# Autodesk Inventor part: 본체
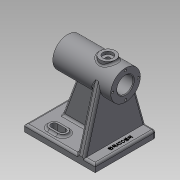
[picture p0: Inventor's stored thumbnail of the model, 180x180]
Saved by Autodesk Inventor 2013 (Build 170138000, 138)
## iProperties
Created: 2019-10
Part Number: 본체
Material: 일반
Document SubType Name: Modeling
Designer: hana-max10
Density: 1 g/cm^3
Author: hana-max10
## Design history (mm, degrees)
sketch "스케치1"
  geometry: L1 (-47.727, 63.797)-(52.273, 63.797); L2 (52.273, 63.797)-(52.273, -22.203); L3 (52.273, -22.203)-(-47.727, -22.203); L4 (-47.727, -22.203)-(-47.727, 63.797); 1 further point
  constraints: 8 end point, 2 parallel, 1 horizontal, 1 perpendicular
  dimensions: "d0" = 100 distance of L2.end L3.end; "d2" = 86 distance of L1.end L2.end
extrude "돌출1" new body sketch "스케치1" distance "d3" = 10; taper "d4" = 0 deg
node "작업 평면1"
sketch "스케치2"
  geometry: L1 (52.273, 63.797)-(-47.727, 63.797) reference; L2 (-47.727, 63.797)-(-47.727, -22.203) reference; L3 (-47.727, -22.203)-(52.273, -22.203) reference; L4 (52.273, -22.203)-(52.273, 63.797) reference; L5 (-47.727, 20.797)-(111.797, 20.797); L6 (52.273, 41.797)-(-29.727, 41.797); L7 (-29.727, 41.797)-(-29.727, 35.297); L8 (-29.727, 35.297)-(32.273, 35.297); L9 (32.273, 35.297)-(32.273, 32.297); L10 (32.273, 32.297)-(52.273, 32.297); L11 (52.273, 32.297)-(52.273, 41.797); 1 further point
  constraints: 14 end point, 4 horizontal, 3 vertical, 1 midpoint
  dimensions: "d6" = 82 distance of L6.start L6.end; "d8" = 9.5 distance of L10.end L6.start; "d9" = 6.5 distance of L6.end L7.end; "d10" = 62 distance of L7.end L8.end; "d11" = 23 diameter of L10 L5; "d12" = 0 distance between parallel lines of L4 L11
revolve "회전1" sketch "스케치2" stored, may be unused: angle "d13" = 90 deg
node "작업 평면2"
sketch "스케치3"
  geometry: L1 (47.727, 0)-(47.727, 10) reference; L2 (32.727, 10)-(-27.273, 10); L3 (-27.273, 10)-(-27.273, 67); L4 (-27.273, 67)-(11.981, 67); L5 (11.981, 67)-(32.727, 10); L6 (-52.273, 0)-(-52.273, 10) reference; L7 (47.727, 10)-(-52.273, 10) reference; L8 (-52.273, 107)-(-52.273, 65) reference; L9 (29.727, 107)-(29.727, 65) reference; 1 further point
  constraints: 8 end point, 2 horizontal, 1 vertical
  dimensions: "d19" = 70 deg angle of L2 L5; "d20" = 15 distance from line of L1 L2.start; "d21" = 25 distance between parallel lines of L6 L3; "d22" = 0 distance between parallel lines of L7 L2; "d23" = 57 distance of L2.end L3.end
extrude "돌출2" join sketch "스케치3" stored distance "d24" = 10; taper "d25" = 0 deg
sketch "스케치4"
  geometry: L1 (0, 0)-(-55.555, 0) reference; L2 (-55.655, 10)-(0, 10) reference; L3 (-81.642, -15.431)-(0, -38.203); L4 (0, -38.203)-(0, 47.797); L5 (0, 47.797)-(-81.642, 25.025); L6 (0, -38.203)-(0, 47.797) reference; L7 (-76, 4.797)-(20.74, 4.797); A1 r 21 centre (-76, 4.797) between (-55.555, 0) and (-55.655, 10) reference; A2 r 21 centre (-76, 4.797) between (-55.655, 10) and (-55.555, 0) reference; A3 r 21 centre (-76, 4.797) between (-81.642, -15.431) and (-81.642, 25.025); 1 further point
  constraints: 8 end point, 3 point on circle, 2 tangent, 1 centre point, 1 coincident, 1 horizontal, 1 vertical, 1 other
  dimensions: "d26" = 0 distance between parallel lines of L4 L6; "d27" = 86 distance of L3.end L4.end
extrude "돌출3" join sketch "스케치4" distance "d28" = 10; taper "d29" = 0 deg
node "작업 평면3"
sketch "스케치5"
  geometry: L1 (-21.727, 52.297)-(-9.727, 52.297); L2 (-21.727, 43.297)-(-9.727, 43.297); L3 (27.273, 63.797)-(-47.727, 63.797) reference; L4 (-47.727, 63.797)-(-47.727, -22.203) reference; L5 (27.273, 16)-(-32.727, 16) reference; L6 (-32.727, 26)-(27.273, 26) reference; L7 (-32.727, 16)-(-32.727, 26) reference; L8 (-32.727, 21)-(62.617, 21); L9 (-47.727, -21.797)-(-47.727, 64.203); L10 (-21.727, 54.797)-(-9.727, 54.797); L11 (-21.727, 40.797)-(-9.727, 40.797); A1 r 4.5 centre (-21.727, 47.797) between (-21.727, 52.297) and (-21.727, 43.297); A2 r 4.5 centre (-9.727, 47.797) between (-9.727, 43.297) and (-9.727, 52.297); A3 r 7 centre (-9.727, 47.797) between (-9.727, 40.797) and (-9.727, 54.797); A4 r 7 centre (-21.727, 47.797) between (-21.727, 54.797) and (-21.727, 40.797)
  constraints: 12 end point, 8 point on circle, 7 tangent, 4 centre point, 2 coincident, 2 symmetric about line, 1 horizontal, 1 midpoint, 1 parallel
  dimensions: "d31" = 9 diameter of A1; "d33" = 9 diameter of A2; "d34" = 16 distance from line of L3 A1.centre; "d35" = 26 distance from line of L4 A1.centre; "d36" = 12 distance of A2.centre A1.centre; "d37" = 16 distance from line of L3 A2.centre; "d39" = 14 diameter of A3; "d41" = 7 radius of A4
extrude "돌출4" join sketch "스케치5" distance "d42" = 3; taper "d43" = 0 deg
sketch "스케치6" dims "d61" = 10
  geometry: L1 (-21.727, 52.297)-(-9.727, 52.297); L2 (-21.727, 43.297)-(-9.727, 43.297); L3 (27.273, 63.797)-(-47.727, 63.797) reference; L4 (-47.727, 63.797)-(-47.727, -22.203) reference; L5 (-21.727, -1.703)-(-9.727, -1.703); L6 (-21.727, -10.703)-(-9.727, -10.703); A1 r 4.5 centre (-21.727, 47.797) between (-21.727, 52.297) and (-21.727, 43.297); A2 r 4.5 centre (-9.727, 47.797) between (-9.727, 43.297) and (-9.727, 52.297); A3 r 4.5 centre (-9.727, -6.203) between (-9.727, -10.703) and (-9.727, -1.703); A4 r 4.5 centre (-21.727, -6.203) between (-21.727, -1.703) and (-21.727, -10.703); 1 further point
  constraints: 8 end point, 8 point on circle, 4 centre point, 3 tangent, 1 parallel, 1 vertical, 10 other
  dimensions: "d44" = 12 distance of A2.centre A1.centre; "d46" = 9 diameter of A2; "d47" = 9 diameter of A1; "d48" = 16 distance from line of A1.centre L3; "d49" = 26 distance from line of L4 A1.centre; "d50" = 16 distance from line of L3 A2.centre; "d58" = 54 distance of L1.start L5.start
extrude "돌출5" cut sketch "스케치6" stored distance "d51" = 3; taper "d52" = 0 deg
fillet "모깎기1" dims "d63" = 3
fillet "모깎기2" dims "d64" = 3
chamfer "모따기1" distance "d65" = 1; stored, may be unused: second distance "d66" = 2, angle "d67" = 45 deg
fillet "모깎기3" dims "d68" = 3
fillet "모깎기4" dims "d69" = 3
node "작업 평면4"
sketch "스케치9"
  geometry: L1 (-52.273, 41.797)-(-52.273, -0.203) reference; L2 (-52.273, 20.797)-(59.849, 20.797); C1 r 11 at (-27.273, 20.797); 2 further points
  constraints: 2 end point, 1 centre point, 1 coincident, 1 horizontal, 1 midpoint, 1 point on line
  dimensions: "d71" = 22 diameter of C1; "d73" = 25 distance from line of L1 C1.centre
extrude "돌출6" join sketch "스케치9" stored distance "d74" = 3; taper "d75" = 0 deg
fillet "모깎기5" dims "d76" = 3
sketch "스케치11"
  geometry: A1 r 11 centre (27.273, 20.797) between (38.273, 20.797) and (16.273, 20.797) reference; 2 further points
  constraints: 1 coincident
hole "구멍1" sketch "스케치11" at (27.273, 20.797) diameter "d77" = 6; stored, may be unused: countersink angle "d81" = 90 deg, drill point angle "d83" = 118 deg; dims "d78" = 6, "d79" = 14, "d80" = 4, "d82" = 20
sketch "스케치12"
  geometry: L1 (40.684, 1.326)-(40.684, 42.805); L2 (40.684, 42.805)-(46.688, 42.805); L3 (46.688, 42.805)-(46.688, 1.326); L4 (46.688, 1.326)-(40.684, 1.326); 1 further point
  constraints: 2 other
feature "엠보싱1" sketch "스케치12" dims "d0" = 100, "d2" = 86, "d13" = 90 deg, "d84" = 0.5, "d85" = 0
sketch "스케치13" dims "d86" = 36
  geometry: L1 (18, 0)-(0, 0); C1 r 15.5 at (0, 0) reference; 2 further points
  constraints: 2 coincident, 2 end point, 1 horizontal, 1 horizontal alignment, 2 other
hole "구멍2" sketch "스케치13" at (18, 0) diameter "d88" = 3.242; stored, may be unused: countersink angle "d92" = 90 deg, drill point angle "d94" = 118 deg; dims "d89" = 6, "d90" = 14, "d91" = 4, "d93" = 8
sketch "스케치14" dims "d19" = 70 deg, "d20" = 15, "d21" = 25, "d22" = 0, "d23" = 57, "d99" = 36
  geometry: L1 (0, 0)-(-18, 0); C1 r 12.5 at (0, 0) reference; 2 further points
  constraints: 2 coincident, 2 end point, 1 horizontal, 1 horizontal alignment, 2 other
hole "구멍3" sketch "스케치14" at (-18, 0) diameter "d100" = 3.242; stored, may be unused: countersink angle "d104" = 90 deg, drill point angle "d106" = 118 deg; dims "d21" = 25, "d101" = 6, "d102" = 14, "d103" = 4, "d105" = 8
node "솔리드1"
pattern_linear "직사각형 패턴1" dims "d55" = 54
pattern_circular "원형 패턴1" dims angle "d96" = 360 deg
pattern_circular "원형 패턴2" dims angle "d108" = 360 deg
node "투영된 루프1"
node "투영된 루프2"
other parameters: "d5" = 76, "d14" = 21, "d30" = 3, "d38" = 14
